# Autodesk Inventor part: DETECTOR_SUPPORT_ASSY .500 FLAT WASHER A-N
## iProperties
Shininess: 64.0
Length Units: 11272
Angle Units: 11279
Time Units: 11290
Mass Units: 11286
Length Display Precision: 3
Angle Display Precision: 2
Compacted: True
Part Number: DETECTOR_SUPPORT_ASSY .500 FLAT WASHER A-N
Document SubType Name: Modeling
Created: 2004-08
Designer: John Blackburn
Material: MILD_STEEL
Manufacturer: Standard
Standards Organization: Custom
Density: 0.0
Volumn: 0.0
Area: 0.0
PropertySet Name: Model Information
Control State: 0
Master: False
Checked Out: False
Author: John Blackburn
